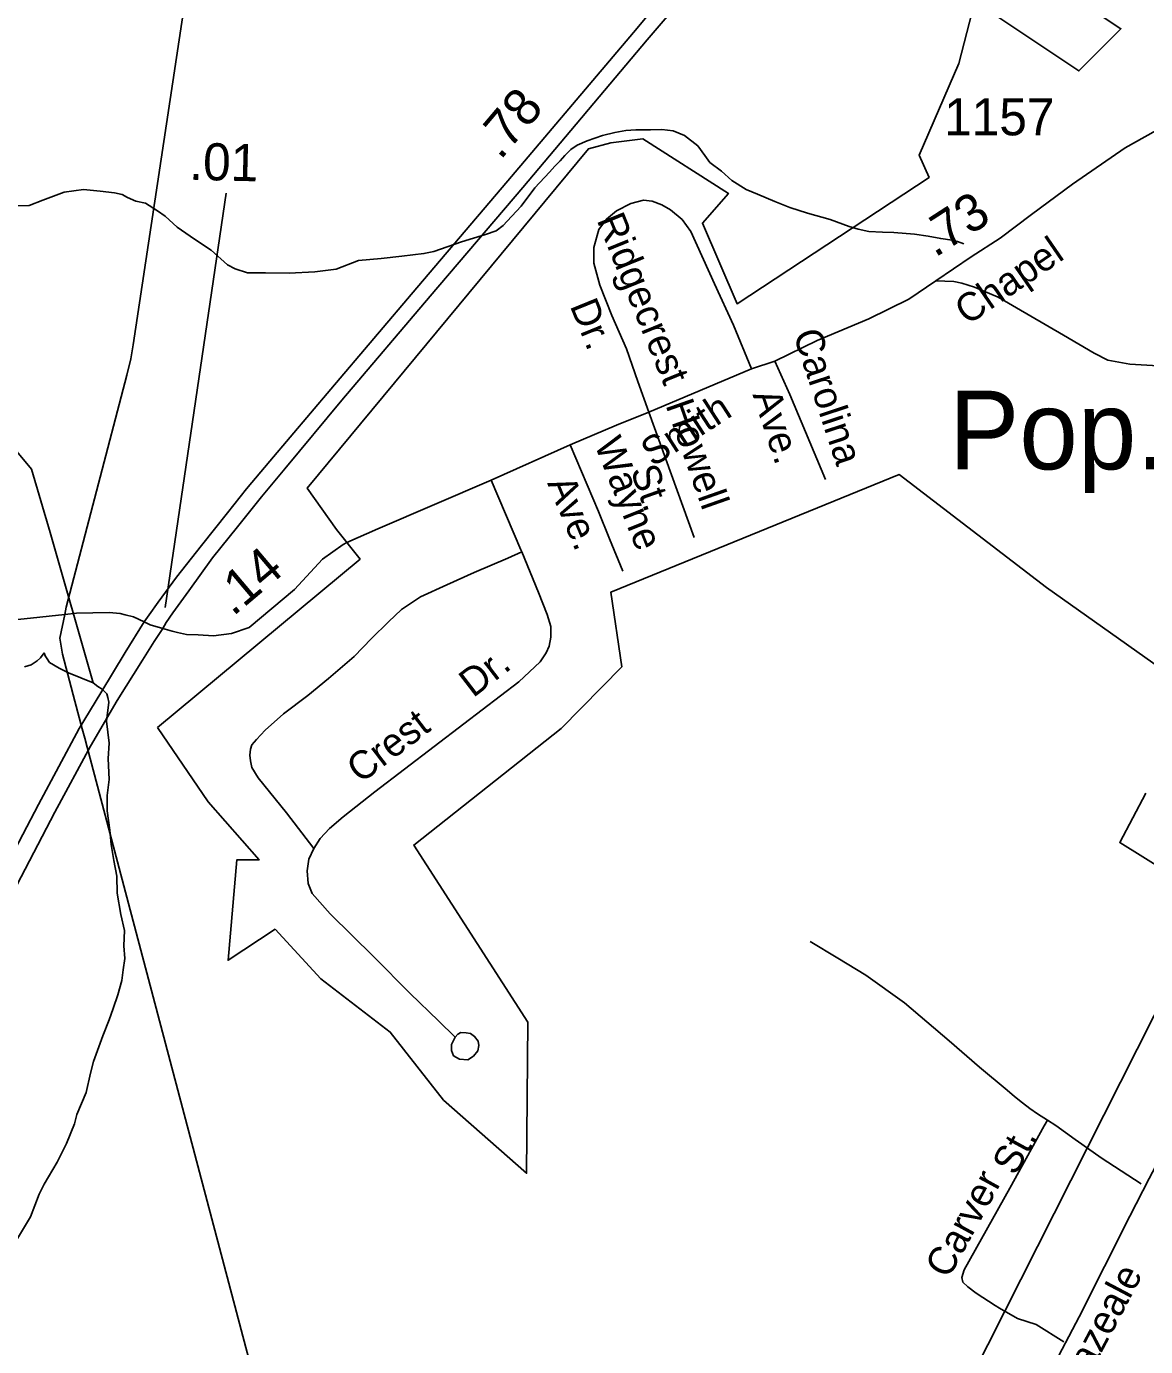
# Model space of a CAD drawing. Extents: x 2206922 to 2357709, y 510027 to 673830.
# Drawn here: x 2272282 to 2276050, y 524252 to 528698 of the extents above; entities that cross this region are included whole.
import ezdxf

# ---------------------------------------------------------------- set-up
doc = ezdxf.new("R2010")
doc.units = 0
for name, color, linetype in [('Exist Boundary Political City Limit New', 7, 'Continuous'), ('Exist Civil Demographics City Label', 7, 'Continuous'), ('Exist Hydrographic Creek Single Shore', 7, 'Continuous'), ('Exist Road Non-System Type 51', 7, 'Continuous'), ('Exist Road Non-System Type 51 Label', 7, 'Continuous'), ('Exist Road Primary US Attributed', 7, 'Continuous'), ('Exist Road Primary US Divided Attributed', 7, 'Continuous'), ('Exist Road Primary US Label', 7, 'Continuous'), ('Exist Road Primary US Mileage Hundredths English Label', 7, 'Continuous'), ('Exist Road Secondary Mileage Hundredths English Label', 7, 'Continuous'), ('Exist Road Secondary Type 51 Attributed', 7, 'Continuous'), ('Exist Road Secondary Type 51 Label', 7, 'Continuous'), ('Exist Road Secondary Type 51 Number Label', 7, 'Continuous'), ('Exist Utilities Electrical Transmission Line', 7, 'Continuous'), ('Map Preparation Boundary City Limit Buffer Line', 7, 'Continuous')]:
    doc.layers.add(name, color=color, linetype=linetype)

msp = doc.modelspace()

# ---------------------------------------------------------------- linework, layer by layer
at = {"layer": 'Exist Boundary Political City Limit New'}
for points in [[(2272723, 526337.2), (2273405.2, 526903.9), (2273326.2, 527003.6), (2273227.5, 527142.5), (2274174.2, 528285.6), (2274249.2, 528306.5), (2274357.8, 528319), (2274645.5, 528135.4), (2274557.8, 528035.3), (2274674.5, 527764.1), (2275321, 528189.7), (2275287.5, 528264.8), (2275421, 528573.5), (2275475.2, 528782.1), (2275825.5, 528548.5), (2275967.2, 528690.4), (2275558.8, 528961.6)], [(2276263.2, 526420.7), (2275717, 526808.8), (2275220.8, 527188.4), (2274249.2, 526792.1), (2274286.8, 526541.7), (2274082.5, 526333.1), (2273586.2, 525940.9), (2273969.8, 525344.3), (2273965.8, 524835.3), (2273686.2, 525081.4), (2273507, 525310.9), (2273273.5, 525490.3), (2273119.2, 525657.2)], [(2273119.2, 525657.2), (2272960.8, 525552.9), (2272990, 525890.9), (2273065, 525890.9), (2272894, 526086.9), (2272723, 526337.2)], [(2276205, 525799.1), (2275963, 525949.2), (2276050.8, 526116.1)], [(2276271.8, 522265.2), (2275788, 522640.8), (2275387.8, 522140.1), (2274858, 522519.8), (2274812.2, 522444.7), (2274674.5, 522511.4), (2274566.2, 522344.5), (2274528.8, 522377.9), (2274418, 522224.9), (2274492.8, 522174.3), (2274381.8, 522010.3), (2274295, 522040), (2274132.5, 522065), (2273944.8, 522056.7), (2274758, 523141.4), (2275070.8, 523629.6), (2275462.8, 524146.9), (2276301, 525807.4)]]:
    msp.add_lwpolyline(points, dxfattribs=at)
at = {"layer": 'Exist Hydrographic Creek Single Shore'}
for points in [[(2275438.4, 527966.2), (2275416.4, 527974), (2275398.4, 527977.9), (2275360.6, 527983.6), (2275318.4, 527991.2), (2275272.5, 527998.5), (2275202.3, 528003.8), (2275164.4, 528005.5), (2275118.5, 528007.2), (2275082.2, 528015), (2275052.5, 528024.4), (2274987.9, 528047.9), (2274912, 528069.1), (2274851.9, 528088.7), (2274801.5, 528108), (2274743.2, 528133.4), (2274705.1, 528149.3), (2274656.9, 528178.8), (2274622.7, 528210.4), (2274582.5, 528240), (2274566.1, 528263.9), (2274542.1, 528295.5), (2274497.8, 528331), (2274459.6, 528346.9), (2274421.5, 528350.6), (2274383.6, 528350.2), (2274333.7, 528349.6), (2274299.9, 528347.4), (2274263.6, 528341.1), (2274221.8, 528330.8), (2274169.9, 528312.3), (2274136.1, 528297.9), (2274114.5, 528283.7), (2274094.7, 528263.6), (2274078.9, 528245.3), (2274061, 528227.3), (2274043.2, 528206.9), (2273993.6, 528154.7), (2273948.2, 528092.2), (2273900.9, 528041.8), (2273886.9, 528027.6), (2273863.2, 528009.3), (2273827.1, 527996.9), (2273747.3, 527972.5), (2273653.8, 527939.5), (2273620.2, 527933.2), (2273545.9, 527924.5), (2273476, 527916), (2273400.1, 527909.2), (2273324.9, 527880.4), (2273252.7, 527871.8), (2273166.6, 527867), (2273086.8, 527868.4), (2273026.7, 527867.7), (2272984.9, 527881.3), (2272958.7, 527895), (2272904.1, 527944.6), (2272847.7, 527981.9), (2272789.3, 528021.5), (2272749.3, 528058.8), (2272722.9, 528076.5), (2272682.9, 528102.4), (2272650.7, 528110.1), (2272622.4, 528121.7), (2272604.5, 528131.7), (2272578.7, 528137.2), (2272530.3, 528142.9), (2272474.3, 528148.4), (2272408.5, 528139.7), (2272336.9, 528113.2), (2272291, 528094.6), (2272251, 528094.1)], [(2271384.3, 528216.2), (2271748.1, 527920.5), (2272048.7, 527507.2), (2272299.2, 527206.5), (2272361.8, 526993.6), (2272506.3, 526487.6)], [(2272275.6, 526541.4), (2272297.4, 526547.5), (2272317.7, 526561.8), (2272329.6, 526571.8), (2272341.1, 526587.9)], [(2272575.6, 525888.3), (2272567.2, 525942.3), (2272562.5, 525990.5), (2272553.9, 526056.3), (2272553.7, 526108.2), (2272560.9, 526162.2), (2272556.6, 526232.2), (2272560, 526284), (2272551, 526357.9), (2272558.8, 526422.1), (2272556.4, 526437.9), (2272552.3, 526449.8), (2272536.3, 526465.6), (2272522.1, 526475.4), (2272506.3, 526487.6), (2272423.9, 526520.7), (2272391.7, 526536.5), (2272359.1, 526556), (2272351.3, 526568.1), (2272345.4, 526577.9), (2272341.1, 526587.9)], [(2272251.6, 524616), (2272295.1, 524688.6), (2272324.4, 524764.8), (2272342.1, 524798.7), (2272385.5, 524873.3), (2272416.7, 524935.4), (2272444.2, 525001.8), (2272451.8, 525033.6), (2272483.2, 525107.9), (2272498.1, 525172.1), (2272508.2, 525212), (2272539.1, 525298.5), (2272560.5, 525352.5), (2272574.4, 525390.5), (2272589.8, 525436.9), (2272603.3, 525484.8), (2272607.2, 525521.1), (2272612.7, 525559.2), (2272610.3, 525600.9), (2272611.7, 525653), (2272599.4, 525706.7), (2272586.9, 525778.8), (2272586.3, 525836.4), (2272575.6, 525888.3)]]:
    msp.add_lwpolyline(points, dxfattribs=at)
at = {"layer": 'Exist Road Non-System Type 51'}
msp.add_line((2274377.9, 527399.3), (2274529.8, 526976.8), dxfattribs=at)
for points in [[(2274722.7, 527545.4), (2274662.5, 527692.3), (2274599.1, 527831.4), (2274519, 528007.8), (2274489.5, 528047.8), (2274450.8, 528080.2), (2274421.5, 528097.2), (2274389, 528109.6), (2274359.7, 528112.7), (2274316.4, 528101.9), (2274268.5, 528077.1), (2274234.6, 528049.3), (2274208.9, 528014.5), (2274192.9, 527953.5), (2274192.9, 527900.9), (2274212.9, 527826.7), (2274253.3, 527724.9), (2274302.7, 527612.1), (2274340.8, 527502.3), (2274377.9, 527399.3)], [(2275343.7, 527841.3), (2275404.2, 527838.5), (2275432, 527833.9), (2275473.7, 527820), (2275554, 527785.9), (2275773.4, 527657.7), (2275876.9, 527597.4), (2275923.3, 527574.2), (2275997.4, 527560.3), (2276130.3, 527552.5), (2276397.5, 527547.9), (2276538.1, 527549.5), (2276581.4, 527557.2), (2276604.5, 527569.5), (2276633.9, 527600.5), (2276677.1, 527648.4)], [(2274801.7, 527571.1), (2274852.7, 527458.3), (2274972.3, 527172.1)], [(2274112.5, 527288.8), (2274208.3, 527064.7), (2274245.4, 526972), (2274290.2, 526863.8)], [(2273846.8, 527169.8), (2273947.1, 526934.9), (2273949.8, 526928.6)], [(2273249.9, 525929), (2273158, 526049.4), (2273062.2, 526166.9), (2273040.6, 526202.4), (2273036, 526224.1), (2273034.4, 526244.1), (2273036, 526264.2), (2273040.6, 526278.1), (2273056, 526296.7), (2273085.4, 526327.6), (2273147.2, 526383.3), (2273229.1, 526445.1), (2273298.6, 526502.3), (2273385.1, 526576.5), (2273443.8, 526636.7), (2273501, 526692.4), (2273544.2, 526734.1), (2273572, 526752.7), (2273609.1, 526777.4), (2273697.1, 526817.6), (2273789.8, 526859.3), (2273902.6, 526907.2), (2273949.8, 526928.6)], [(2273949.8, 526928.6), (2274005.9, 526791.1), (2274035.3, 526716.9), (2274047.6, 526676.7), (2274047.6, 526641.2), (2274041.5, 526610.3), (2274032.2, 526588.6), (2274012.1, 526557.7), (2273939.4, 526490.8), (2273754.8, 526349.1), (2273455.1, 526120.5), (2273348, 526035.4), (2273302.3, 525997.2), (2273270.6, 525962.8), (2273249.9, 525929)], [(2273249.9, 525929), (2273232.2, 525893.3), (2273227.5, 525854.6), (2273230.6, 525811.3), (2273244.5, 525777.3), (2273304.8, 525709.3), (2273451.5, 525564), (2273573.6, 525440.4), (2273669.3, 525349.2), (2273725, 525293.5)], [(2274920.3, 525616.4), (2275013.7, 525559.4), (2275107.7, 525503.1), (2275238.2, 525409.6), (2275388.6, 525281.2), (2275490.9, 525193.2), (2275583.9, 525115.3), (2275609, 525093.6), (2275635.4, 525073), (2275660.1, 525053.4), (2275685.9, 525035.2), (2275719.5, 525013.9)], [(2273725, 525293.5), (2273734.8, 525303.5), (2273744.7, 525309.7), (2273762.7, 525308), (2273776.8, 525306.1), (2273790.8, 525296.2), (2273802.9, 525280.2), (2273805.2, 525266.3), (2273801.3, 525248.2), (2273787.5, 525230.1), (2273767.7, 525217.9), (2273739.5, 525219.7), (2273719.6, 525231.5), (2273713.3, 525249.4), (2273713.1, 525269.4), (2273725, 525293.5)], [(2275719.5, 525013.9), (2275708.5, 524995.4), (2275592.7, 524785.2), (2275439.7, 524510), (2275432, 524483.8), (2275435.1, 524468.3), (2275452.1, 524452.9), (2275479.9, 524431.2), (2275543.2, 524389.5), (2275558.7, 524380.6)], [(2275719.5, 525013.9), (2275747.7, 524996.8), (2275813.6, 524949.4), (2275835.4, 524933.9)], [(2275835.4, 524933.9), (2275901.1, 524887.5), (2276035, 524800)], [(2275558.7, 524380.6), (2275618.9, 524346.2), (2275682, 524325.8), (2275775, 524268.1)]]:
    msp.add_lwpolyline(points, dxfattribs=at)
at = {"layer": 'Exist Road Primary US Attributed'}
msp.add_lwpolyline([(2275505.2, 523730.3), (2275769.4, 524243.4), (2275826.9, 524351.4), (2275997.3, 524691.3), (2276061.9, 524817.5), (2276106.9, 524902.7), (2276141.6, 524976), (2276320.6, 525315.9), (2276558, 525782.7), (2276633.7, 525933.4), (2276708.6, 526084), (2276774, 526207.8), (2276852.1, 526354.5), (2276879.7, 526407.3), (2276900.2, 526436.5), (2276993.3, 526577.7), (2277078.4, 526703.8), (2277156.5, 526819), (2277413.6, 527186.5), (2277662, 527549.2), (2277938, 527945.9)], dxfattribs=at)
at = {"layer": 'Exist Road Primary US Divided Attributed'}
for points in [[(2275315.9, 529858.2), (2274901.4, 529369.8), (2274529.4, 528922.9), (2274325.7, 528677.9), (2273903.1, 528178.4), (2273596.5, 527817.3), (2273306.7, 527476.9), (2273101.1, 527233.7), (2273022.6, 527140.2), (2272959, 527059.7), (2272871.6, 526950.2), (2272787, 526842.7), (2272725.9, 526758.5), (2272694.8, 526716.7), (2272678.5, 526692.5)], [(2272740.9, 526670.8), (2272752.3, 526690.8), (2272774.7, 526722.8), (2272829, 526797.6), (2272908.5, 526908.2), (2272992.7, 527013), (2273073.1, 527114), (2273151.6, 527207.5), (2273344.1, 527439.5), (2273641.4, 527789.3), (2273953.6, 528155.9), (2274372.4, 528653.5), (2274572.4, 528889.2), (2274952, 529339.1), (2275360.2, 529823.2)], [(2272678.5, 526692.5), (2272614.8, 526588.9), (2272532.7, 526453.6), (2272459.8, 526333.9), (2272323, 526077), (2272110.2, 525673.6), (2271940.7, 525348.9), (2271740, 524962.7), (2271431.6, 524343.5), (2271242.7, 523980.6), (2271081.9, 523671.3), (2270883.7, 523288.6), (2270755.2, 523042.7), (2270596.1, 522741), (2270534.4, 522619.4)], [(2270599.4, 522615.5), (2270651.9, 522718.7), (2270813.9, 523023.2), (2270953.5, 523297), (2271140.6, 523649), (2271300.7, 523958.2), (2271487.7, 524330.4), (2271796.1, 524938.4), (2271999.9, 525329.4), (2272162.6, 525641.8), (2272377.6, 526051.4), (2272497.2, 526274.1), (2272587, 526427.4), (2272672.8, 526563.5), (2272711.5, 526626.3), (2272740.9, 526670.8)]]:
    msp.add_lwpolyline(points, dxfattribs=at)
at = {"layer": 'Exist Road Secondary Mileage Hundredths English Label'}
msp.add_line((2272749.4, 526741.1), (2272954.3, 528136.8), dxfattribs=at)
at = {"layer": 'Exist Road Secondary Type 51 Attributed'}
for points in [[(2272740.9, 526670.8), (2272773.1, 526661.3), (2272791, 526657.2), (2272821, 526650.5), (2272859.7, 526648.9), (2272912.2, 526645.8), (2272972.4, 526653.5), (2273031.9, 526673.3), (2273184.1, 526801.9), (2273278.3, 526904), (2273347.8, 526953.4), (2273361.2, 526959.4), (2273465.2, 527006), (2273846.8, 527169.8), (2274112.5, 527288.8), (2274268.5, 527355.3), (2274377.9, 527399.3), (2274722.7, 527545.4), (2274801.7, 527571.1), (2274943.8, 527640.6), (2275118.4, 527713.3), (2275252.8, 527779.8), (2275343.7, 527841.3), (2275462.9, 527922.3), (2275560.4, 527985.3), (2275665.5, 528064.2), (2275804.5, 528167.3), (2275981.3, 528288.9), (2276152.2, 528384.4)], [(2270005, 526279.2), (2270072.5, 526266.2), (2270177.6, 526253.6), (2270285.5, 526250.6), (2270392.6, 526257.9), (2270468.3, 526267.1), (2270604.2, 526302.7), (2270701.5, 526327.4), (2270971.9, 526404.7), (2271316.5, 526518.2), (2271631.5, 526614.9), (2271761.3, 526647.4), (2271844.7, 526661.3), (2271940.5, 526672.1), (2272116.6, 526687.6), (2272274.2, 526703), (2272410.7, 526717.4), (2272450.3, 526721.6), (2272560, 526724.7), (2272597.5, 526720.6), (2272613.8, 526716.6), (2272641.9, 526709.8), (2272678.5, 526692.5)], [(2272678.5, 526692.5), (2272698.9, 526682.8), (2272740.9, 526670.8)]]:
    msp.add_lwpolyline(points, dxfattribs=at)
at = {"layer": 'Exist Utilities Electrical Transmission Line'}
for p, q in [((2272445.2, 526425.4), (2272469.8, 526332.3)), ((2272469.8, 526332.3), (2272478, 526301.4)), ((2272478, 526301.4), (2272486.2, 526270.5)), ((2272486.2, 526270.5), (2272510.8, 526177.4)), ((2272510.8, 526177.4), (2273235.2, 523438.1))]:
    msp.add_line(p, q, dxfattribs=at)
for points in [[(2273024.5, 530164.7), (2272641.3, 527626), (2272633.7, 527578), (2272620.2, 527523.9), (2272415.8, 526742.3), (2272410.7, 526717.4)], [(2272410.7, 526717.4), (2272394.7, 526638.2), (2272403.2, 526584.3), (2272445.2, 526425.4)]]:
    msp.add_lwpolyline(points, dxfattribs=at)
at = {"layer": 'Map Preparation Boundary City Limit Buffer Line'}
for points in [[(2272723, 526337.2), (2273405.2, 526903.9), (2273326.2, 527003.6), (2273227.5, 527142.5), (2274174.2, 528285.6), (2274249.2, 528306.5), (2274357.8, 528319), (2274645.5, 528135.4), (2274557.8, 528035.3), (2274674.5, 527764.1), (2275321, 528189.7), (2275287.5, 528264.8), (2275421, 528573.5), (2275475.2, 528782.1), (2275825.5, 528548.5), (2275967.2, 528690.4), (2275558.8, 528961.6)], [(2276263.2, 526420.7), (2275717, 526808.8), (2275220.8, 527188.4), (2274249.2, 526792.1), (2274286.8, 526541.7), (2274082.5, 526333.1), (2273586.2, 525940.9), (2273969.8, 525344.3), (2273965.8, 524835.3), (2273686.2, 525081.4), (2273507, 525310.9), (2273273.5, 525490.3), (2273119.2, 525657.2)], [(2273119.2, 525657.2), (2272960.8, 525552.9), (2272990, 525890.9), (2273065, 525890.9), (2272894, 526086.9), (2272723, 526337.2)], [(2276205, 525799.1), (2275963, 525949.2), (2276050.8, 526116.1)], [(2276271.8, 522265.2), (2275788, 522640.8), (2275387.8, 522140.1), (2274858, 522519.8), (2274812.2, 522444.7), (2274674.5, 522511.4), (2274566.2, 522344.5), (2274528.8, 522377.9), (2274418, 522224.9), (2274492.8, 522174.3), (2274381.8, 522010.3), (2274295, 522040), (2274132.5, 522065), (2273944.8, 522056.7), (2274758, 523141.4), (2275070.8, 523629.6), (2275462.8, 524146.9), (2276301, 525807.4)]]:
    msp.add_lwpolyline(points, dxfattribs=at)

# ---------------------------------------------------------------- texts
at = {"layer": 'Exist Civil Demographics City Label'}
msp.add_text('Pop. 4,596', height=265, dxfattribs=at).set_placement((2275388.7, 527206.3))
at = {"layer": 'Exist Road Non-System Type 51 Label'}
for s, rotation, p in [('Ridgecrest', 292.1429, (2274201, 528046.3)), ('Dr.', 292.1429, (2274110.6, 527757.4)), ('Carolina', 288.2359, (2274862.6, 527662.3)), ('Ave.', 288.2359, (2274726.2, 527458)), ('Howell', 289.3879, (2274433.1, 527423.1)), ('Wayne', 291.8137, (2274192.7, 527292.1)), ('St.', 289.3879, (2274314.9, 527203.1)), ('Ave.', 292.6996, (2274034.7, 527159.9)), ('Dr.', 37.51, (2273785.8, 526435)), ('Crest', 37.3348, (2273406.9, 526145.7)), ('St.', 61.3151, (2275612.3, 524823.9)), ('Carver', 61.3151, (2275386.3, 524476.9))]:
    msp.add_text(s, height=95, rotation=rotation, dxfattribs=at).set_placement(p)
at = {"layer": 'Exist Road Primary US Label'}
msp.add_text('Breazeale', height=95, rotation=62.1616, dxfattribs=at).set_placement((2275775.4, 523990))
at = {"layer": 'Exist Road Primary US Mileage Hundredths English Label'}
msp.add_text('.78', height=125, rotation=49.7706, dxfattribs=at).set_placement((2273877.8, 528245.2))
at = {"layer": 'Exist Road Secondary Mileage Hundredths English Label'}
for s, rotation, p in [('.01', 358.5847, (2272828.9, 528181.9)), ('.73', 32.8695, (2275340.9, 527917.9)), ('.14', 40.2106, (2272977.1, 526708.8))]:
    msp.add_text(s, height=125, rotation=rotation, dxfattribs=at).set_placement(p)
at = {"layer": 'Exist Road Secondary Type 51 Label'}
for s, rotation, p in [('Chapel', 34.5201, (2275450.2, 527689.6)), ('Smith', 32.8695, (2274391, 527212.6))]:
    msp.add_text(s, height=95, rotation=rotation, dxfattribs=at).set_placement(p)
at = {"layer": 'Exist Road Secondary Type 51 Number Label'}
msp.add_text('1157', height=125, dxfattribs=at).set_placement((2275371.7, 528331.3))

doc.saveas('drawing.dxf')
